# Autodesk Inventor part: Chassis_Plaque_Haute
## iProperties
Created: 2009-01
Part Number: Chassis_Plaque_Haute
Document SubType Name: Sheet Metal
Designer: claivier
Author: claivier
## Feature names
1. Perçage1 [Hole]
2. Perçage2 [Hole]
3. Perçage3 [Hole]
4. Perçage4 [Hole]
5. Perçage5 [Hole]
6. Perçage6 [Hole]
7. Extrusion1
8. Extrusion2
9. Chanfrein de coin1
10. Chanfrein de coin2
11. Perçage7 [Hole]
12. Miroir1 [Mirror]
13. Extrusion3
14. Plaque1
15. Pli1
16. Couper1
17. Couper2
